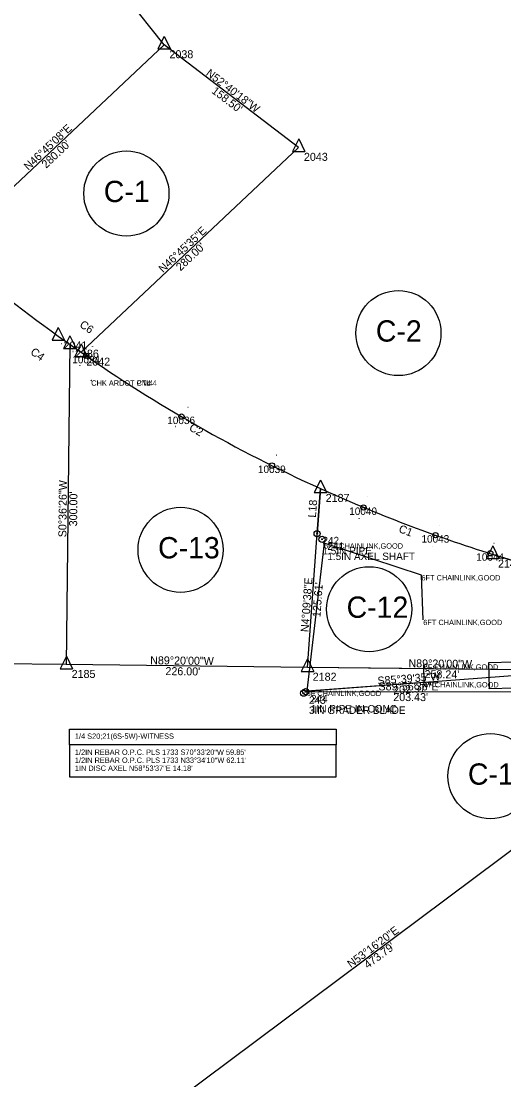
# Model space of a CAD drawing. Extents: x 1431802 to 1457777, y 1852108 to 1876350.
# Drawn here: x 1443202 to 1443655, y 1854558 to 1855549 of the extents above; entities that cross this region are included whole.
import ezdxf

# ---------------------------------------------------------------- set-up
doc = ezdxf.new("R2010")
doc.units = 0
for name, color, linetype in [('Default', 7, 'Continuous'), ('S_BUILDING', 7, 'Continuous'), ('S_CAL_CORNER', 7, 'Continuous'), ('S_CAL_CORNER_ANNOT', 7, 'Continuous'), ('S_EXISTING_ALIGNMENT', 7, 'Continuous'), ('S_EXISTING_ALIGNMENT_ANNOT', 7, 'Continuous'), ('S_FENCE', 7, 'Continuous'), ('S_FENCE_ANNOT', 7, 'Continuous'), ('S_IRON_PIN', 7, 'Continuous'), ('S_IRON_PIN_ANNOT', 7, 'Continuous'), ('S_MSC_PT_SYM', 7, 'Continuous'), ('S_PROPERTY', 7, 'Continuous'), ('S_PROPERTY_ANNOT', 7, 'Continuous'), ('S_PROPERTY_TEXT', 7, 'Continuous'), ('S_QSECTION', 7, 'Continuous'), ('S_QSECTION_ANNOT', 7, 'Continuous'), ('S_RDW_PT_SYM', 7, 'Continuous'), ('S_STR_PT_SYM', 7, 'Continuous'), ('S_SURVEY_TEXT_ANNOT', 7, 'Continuous')]:
    doc.layers.add(name, color=color, linetype=linetype)

msp = doc.modelspace()

# ---------------------------------------------------------------- linework, layer by layer
at = {"layer": 'Default'}
for points in [[(1443240.35, 1855247.27), (1443240.38, 1855247.31), (1443240.35, 1855247.27), (1443240.31, 1855247.3), (1443240.35, 1855247.27), (1443240.32, 1855247.23), (1443240.35, 1855247.27), (1443240.39, 1855247.24)], [(1443251.05, 1855239.66), (1443251.08, 1855239.71), (1443251.05, 1855239.66), (1443251.01, 1855239.69), (1443251.05, 1855239.66), (1443251.03, 1855239.62), (1443251.05, 1855239.66), (1443251.1, 1855239.64)], [(1443365.94, 1855166.79), (1443365.96, 1855166.83), (1443365.94, 1855166.79), (1443365.89, 1855166.81), (1443365.94, 1855166.79), (1443365.91, 1855166.74), (1443365.94, 1855166.79), (1443365.98, 1855166.76)], [(1443477.64, 1855090.52), (1443477.59, 1855090.52), (1443477.64, 1855090.52), (1443477.63, 1855090.47), (1443477.64, 1855090.52), (1443477.69, 1855090.51), (1443477.64, 1855090.52), (1443477.64, 1855090.57)], [(1443561.39, 1855074.57), (1443561.41, 1855074.62), (1443561.39, 1855074.57), (1443561.34, 1855074.59), (1443561.39, 1855074.57), (1443561.37, 1855074.53), (1443561.39, 1855074.57), (1443561.43, 1855074.56)]]:
    msp.add_lwpolyline(points, dxfattribs=at)
at = {"layer": 'S_BUILDING'}
for p, q in [((1443664.71, 1854948.82), (1443640.45, 1854948.13)), ((1443640.45, 1854948.13), (1443641.13, 1854923.94)), ((1443641.13, 1854923.94), (1443665.32, 1854924.65))]:
    msp.add_line(p, q, dxfattribs=at)
at = {"layer": 'S_CAL_CORNER'}
for p, q in [((1443336.55, 1855534.92), (1443330.67, 1855523.1)), ((1443336.55, 1855534.92), (1443342.36, 1855523.1)), ((1443330.67, 1855523.1), (1443342.36, 1855523.1)), ((1443462.59, 1855438.81), (1443456.71, 1855426.99)), ((1443462.59, 1855438.81), (1443468.4, 1855426.99)), ((1443456.71, 1855426.99), (1443468.4, 1855426.99)), ((1443237.26, 1855262.17), (1443231.39, 1855250.35)), ((1443237.26, 1855262.17), (1443243.08, 1855250.35)), ((1443231.39, 1855250.35), (1443243.08, 1855250.35)), ((1443248.01, 1855254.45), (1443242.14, 1855242.63)), ((1443248.01, 1855254.45), (1443253.83, 1855242.63)), ((1443242.14, 1855242.63), (1443253.83, 1855242.63)), ((1443258.61, 1855246.99), (1443252.73, 1855235.18)), ((1443258.61, 1855246.99), (1443264.42, 1855235.18)), ((1443252.73, 1855235.18), (1443264.42, 1855235.18)), ((1443483, 1855119.34), (1443477.13, 1855107.52)), ((1443483, 1855119.34), (1443477.13, 1855107.52)), ((1443483, 1855119.34), (1443488.82, 1855107.52)), ((1443483, 1855119.34), (1443488.82, 1855107.52)), ((1443477.13, 1855107.52), (1443488.82, 1855107.52)), ((1443477.13, 1855107.52), (1443488.82, 1855107.52)), ((1443644.51, 1855057.73), (1443638.64, 1855045.91)), ((1443644.51, 1855057.73), (1443638.64, 1855045.91)), ((1443644.51, 1855057.73), (1443650.33, 1855045.91)), ((1443644.51, 1855057.73), (1443650.33, 1855045.91)), ((1443638.64, 1855045.91), (1443650.33, 1855045.91)), ((1443638.64, 1855045.91), (1443650.33, 1855045.91)), ((1443244.83, 1854954.47), (1443238.96, 1854942.65)), ((1443244.83, 1854954.47), (1443250.65, 1854942.65)), ((1443470.82, 1854951.84), (1443464.94, 1854940.02)), ((1443470.82, 1854951.84), (1443464.94, 1854940.02)), ((1443470.82, 1854951.84), (1443476.63, 1854940.02)), ((1443470.82, 1854951.84), (1443476.63, 1854940.02)), ((1443238.96, 1854942.65), (1443250.65, 1854942.65)), ((1443464.94, 1854940.02), (1443476.63, 1854940.02)), ((1443464.94, 1854940.02), (1443476.63, 1854940.02))]:
    msp.add_line(p, q, dxfattribs=at)
at = {"layer": 'S_EXISTING_ALIGNMENT'}
for centre in [(1443263.49, 1855235.69), (1443352.7, 1855178.76), (1443437.52, 1855132.92), (1443523.35, 1855093.66), (1443590.8, 1855067.71), (1443642.19, 1855050.75)]:
    msp.add_circle(centre, 2.5, dxfattribs=at)
at = {"layer": 'S_FENCE'}
for p, q in [((1443486.36, 1855060.08), (1443470.09, 1854922.04)), ((1443577.66, 1855030.3), (1443486.36, 1855060.08)), ((1443579.37, 1854988.47), (1443577.66, 1855030.3)), ((1443580.24, 1854930.1), (1443579.85, 1854946.67)), ((1443470.09, 1854922.04), (1443580.24, 1854930.1))]:
    msp.add_line(p, q, dxfattribs=at)
at = {"layer": 'S_IRON_PIN'}
for centre, radius in [((1443479.84, 1855069.13), 2.91), ((1443479.84, 1855069.13), 0.411), ((1443479.84, 1855069.13), 0.262), ((1443479.84, 1855069.13), 0.212), ((1443479.84, 1855069.13), 0.145), ((1443479.84, 1855069.13), 0.0822), ((1443479.84, 1855069.13), 0.0581), ((1443484.43, 1855063.87), 2.91), ((1443484.43, 1855063.87), 0.411), ((1443484.43, 1855063.87), 0.262), ((1443484.43, 1855063.87), 0.212), ((1443484.43, 1855063.87), 0.145), ((1443484.43, 1855063.87), 0.0822), ((1443484.43, 1855063.87), 0.0581), ((1443469.08, 1854921.13), 2.91), ((1443467.24, 1854919.74), 2.91), ((1443467.24, 1854919.74), 0.411), ((1443467.24, 1854919.74), 0.262), ((1443467.24, 1854919.74), 0.212), ((1443467.24, 1854919.74), 0.145), ((1443467.24, 1854919.74), 0.0822), ((1443467.24, 1854919.74), 0.0581), ((1443469.08, 1854921.13), 0.411), ((1443469.08, 1854921.13), 0.262), ((1443469.08, 1854921.13), 0.212), ((1443469.08, 1854921.13), 0.145), ((1443469.08, 1854921.13), 0.0822), ((1443469.08, 1854921.13), 0.0581)]:
    msp.add_circle(centre, radius, dxfattribs=at)
at = {"layer": 'S_MSC_PT_SYM'}
for points in [[(1443268.11, 1855212.7), (1443268.11, 1855212.75), (1443268.11, 1855212.7), (1443268.06, 1855212.7), (1443268.11, 1855212.7), (1443268.11, 1855212.65), (1443268.11, 1855212.7), (1443268.17, 1855212.7)], [(1443268.12, 1855212.72), (1443268.12, 1855212.77), (1443268.12, 1855212.72), (1443268.07, 1855212.72), (1443268.12, 1855212.72), (1443268.12, 1855212.67), (1443268.12, 1855212.72), (1443268.17, 1855212.72)], [(1443268.13, 1855212.71), (1443268.13, 1855212.76), (1443268.13, 1855212.71), (1443268.08, 1855212.71), (1443268.13, 1855212.71), (1443268.13, 1855212.66), (1443268.13, 1855212.71), (1443268.18, 1855212.71)], [(1443268.13, 1855212.69), (1443268.13, 1855212.74), (1443268.13, 1855212.69), (1443268.08, 1855212.69), (1443268.13, 1855212.69), (1443268.13, 1855212.64), (1443268.13, 1855212.69), (1443268.18, 1855212.69)], [(1443268.13, 1855212.69), (1443268.13, 1855212.74), (1443268.13, 1855212.69), (1443268.08, 1855212.69), (1443268.13, 1855212.69), (1443268.13, 1855212.64), (1443268.13, 1855212.69), (1443268.18, 1855212.69)], [(1443268.13, 1855212.67), (1443268.13, 1855212.72), (1443268.13, 1855212.67), (1443268.08, 1855212.67), (1443268.13, 1855212.67), (1443268.13, 1855212.62), (1443268.13, 1855212.67), (1443268.18, 1855212.67)], [(1443268.15, 1855212.74), (1443268.15, 1855212.79), (1443268.15, 1855212.74), (1443268.09, 1855212.74), (1443268.15, 1855212.74), (1443268.15, 1855212.69), (1443268.15, 1855212.74), (1443268.2, 1855212.74)], [(1443268.15, 1855212.73), (1443268.15, 1855212.78), (1443268.15, 1855212.73), (1443268.1, 1855212.73), (1443268.15, 1855212.73), (1443268.15, 1855212.68), (1443268.15, 1855212.73), (1443268.2, 1855212.73)], [(1443268.15, 1855212.73), (1443268.15, 1855212.78), (1443268.15, 1855212.73), (1443268.1, 1855212.73), (1443268.15, 1855212.73), (1443268.15, 1855212.68), (1443268.15, 1855212.73), (1443268.2, 1855212.73)], [(1443268.15, 1855212.69), (1443268.15, 1855212.74), (1443268.15, 1855212.69), (1443268.1, 1855212.69), (1443268.15, 1855212.69), (1443268.15, 1855212.64), (1443268.15, 1855212.69), (1443268.2, 1855212.69)], [(1443486.36, 1855060.08), (1443486.36, 1855060.13), (1443486.36, 1855060.08), (1443486.31, 1855060.08), (1443486.36, 1855060.08), (1443486.36, 1855060.03), (1443486.36, 1855060.08), (1443486.42, 1855060.08)], [(1443577.66, 1855030.3), (1443577.66, 1855030.35), (1443577.66, 1855030.3), (1443577.61, 1855030.3), (1443577.66, 1855030.3), (1443577.66, 1855030.25), (1443577.66, 1855030.3), (1443577.71, 1855030.3)], [(1443579.37, 1854988.47), (1443579.37, 1854988.52), (1443579.37, 1854988.47), (1443579.32, 1854988.47), (1443579.37, 1854988.47), (1443579.37, 1854988.42), (1443579.37, 1854988.47), (1443579.42, 1854988.47)], [(1443579.85, 1854946.67), (1443579.85, 1854946.72), (1443579.85, 1854946.67), (1443579.8, 1854946.67), (1443579.85, 1854946.67), (1443579.85, 1854946.62), (1443579.85, 1854946.67), (1443579.9, 1854946.67)], [(1443580.24, 1854930.1), (1443580.24, 1854930.15), (1443580.24, 1854930.1), (1443580.19, 1854930.1), (1443580.24, 1854930.1), (1443580.24, 1854930.05), (1443580.24, 1854930.1), (1443580.29, 1854930.1)], [(1443470.09, 1854922.04), (1443470.09, 1854922.09), (1443470.09, 1854922.04), (1443470.04, 1854922.04), (1443470.09, 1854922.04), (1443470.09, 1854921.99), (1443470.09, 1854922.04), (1443470.14, 1854922.04)]]:
    msp.add_lwpolyline(points, dxfattribs=at)
at = {"layer": 'S_PROPERTY'}
for p, q in [((1443336.46, 1855526.94), (1443149.86, 1855761.85)), ((1443132.51, 1855335.1), (1443336.46, 1855526.94)), ((1443462.5, 1855430.83), (1443336.46, 1855526.94)), ((1443258.52, 1855239.01), (1443462.5, 1855430.83)), ((1443247.92, 1855246.47), (1443244.74, 1854946.49)), ((1443482.91, 1855111.36), (1443479.84, 1855069.13)), ((1443479.84, 1855069.13), (1443482.91, 1855111.36)), ((1443470.73, 1854943.86), (1443479.84, 1855069.13)), ((1443470.73, 1854943.86), (1443479.84, 1855069.13)), ((1443730.75, 1855022.75), (1443644.42, 1855049.75)), ((1443644.42, 1855049.75), (1443691.79, 1855034.93)), ((1443644.42, 1855049.75), (1443691.79, 1855034.93)), ((1443244.74, 1854946.49), (1442408.47, 1854956.22)), ((1443671.13, 1854941.53), (1443470.73, 1854943.86)), ((1443671.47, 1854936.49), (1443469.08, 1854921.13)), ((1443469.08, 1854921.13), (1443672.51, 1854920.93)), ((1443347.68, 1854538.17), (1443727.41, 1854821.5))]:
    msp.add_line(p, q, dxfattribs=at)
for centre in [(1443301.02, 1855387.69), (1443556.05, 1855257.01), (1443351.91, 1855053.97), (1443528.65, 1854998.3), (1443642.38, 1854841.97)]:
    msp.add_circle(centre, 39.9, dxfattribs=at)
for centre, radius, start, end in [((1444500.97, 1856997.21), 2152.97, 230.53452, 234.05567), ((1444065.88, 1856397.14), 1411.77, 234.05567, 234.59274), ((1444065.88, 1856397.14), 1411.77, 234.59274, 235.11858), ((1444065.88, 1856397.14), 1411.77, 235.11858, 245.61073), ((1444065.88, 1856397.14), 1411.77, 245.61073, 252.63058), ((1444065.88, 1856397.14), 1411.77, 245.61073, 252.63058)]:
    msp.add_arc(centre, radius, start, end, dxfattribs=at)
at = {"layer": 'S_PROPERTY_TEXT'}
for points in [[(1443247.75, 1854886.04), (1443497.74, 1854886.04), (1443497.74, 1854871.41), (1443247.75, 1854871.41)], [(1443247.75, 1854841.27), (1443497.74, 1854841.27), (1443497.74, 1854871.41), (1443247.75, 1854871.41)]]:
    msp.add_lwpolyline(points, close=True, dxfattribs=at)
at = {"layer": 'S_QSECTION'}
for p, q in [((1443470.73, 1854943.86), (1443244.74, 1854946.49)), ((1443728.95, 1854940.85), (1443470.73, 1854943.86))]:
    msp.add_line(p, q, dxfattribs=at)
at = {"layer": 'S_RDW_PT_SYM'}
for points in [[(1443269.37, 1855244.31), (1443269.37, 1855244.36), (1443269.37, 1855244.31), (1443269.32, 1855244.31), (1443269.37, 1855244.31), (1443269.37, 1855244.26), (1443269.37, 1855244.31), (1443269.42, 1855244.31)], [(1443257.38, 1855226.76), (1443257.38, 1855226.81), (1443257.38, 1855226.76), (1443257.33, 1855226.76), (1443257.38, 1855226.76), (1443257.38, 1855226.71), (1443257.38, 1855226.76), (1443257.43, 1855226.76)], [(1443358.77, 1855187.6), (1443358.77, 1855187.66), (1443358.77, 1855187.6), (1443358.72, 1855187.6), (1443358.77, 1855187.6), (1443358.77, 1855187.55), (1443358.77, 1855187.6), (1443358.82, 1855187.6)], [(1443346.99, 1855169.59), (1443346.99, 1855169.64), (1443346.99, 1855169.59), (1443346.94, 1855169.59), (1443346.99, 1855169.59), (1443346.99, 1855169.54), (1443346.99, 1855169.59), (1443347.04, 1855169.59)], [(1443441.63, 1855142.55), (1443441.63, 1855142.6), (1443441.63, 1855142.55), (1443441.58, 1855142.55), (1443441.63, 1855142.55), (1443441.63, 1855142.51), (1443441.63, 1855142.55), (1443441.68, 1855142.55)], [(1443434.07, 1855122.29), (1443434.07, 1855122.34), (1443434.07, 1855122.29), (1443434.02, 1855122.29), (1443434.07, 1855122.29), (1443434.07, 1855122.24), (1443434.07, 1855122.29), (1443434.12, 1855122.29)], [(1443527.29, 1855103.54), (1443527.29, 1855103.58), (1443527.29, 1855103.54), (1443527.24, 1855103.54), (1443527.29, 1855103.54), (1443527.29, 1855103.48), (1443527.29, 1855103.54), (1443527.34, 1855103.54)], [(1443519.2, 1855083.17), (1443519.2, 1855083.22), (1443519.2, 1855083.17), (1443519.15, 1855083.17), (1443519.2, 1855083.17), (1443519.2, 1855083.12), (1443519.2, 1855083.17), (1443519.25, 1855083.17)], [(1443594.36, 1855077), (1443594.36, 1855077.05), (1443594.36, 1855077), (1443594.31, 1855077), (1443594.36, 1855077), (1443594.36, 1855076.95), (1443594.36, 1855077), (1443594.41, 1855077)], [(1443588.05, 1855057.16), (1443588.05, 1855057.21), (1443588.05, 1855057.16), (1443588, 1855057.16), (1443588.05, 1855057.16), (1443588.05, 1855057.11), (1443588.05, 1855057.16), (1443588.1, 1855057.16)], [(1443645.63, 1855060.19), (1443645.63, 1855060.24), (1443645.63, 1855060.19), (1443645.58, 1855060.19), (1443645.63, 1855060.19), (1443645.63, 1855060.14), (1443645.63, 1855060.19), (1443645.68, 1855060.19)], [(1443640.41, 1855039.87), (1443640.41, 1855039.92), (1443640.41, 1855039.87), (1443640.36, 1855039.87), (1443640.41, 1855039.87), (1443640.41, 1855039.82), (1443640.41, 1855039.87), (1443640.46, 1855039.87)]]:
    msp.add_lwpolyline(points, dxfattribs=at)
at = {"layer": 'S_STR_PT_SYM'}
for points in [[(1443640.45, 1854948.13), (1443640.45, 1854948.18), (1443640.45, 1854948.13), (1443640.4, 1854948.13), (1443640.45, 1854948.13), (1443640.45, 1854948.08), (1443640.45, 1854948.13), (1443640.5, 1854948.13)], [(1443641.13, 1854923.94), (1443641.13, 1854923.99), (1443641.13, 1854923.94), (1443641.08, 1854923.94), (1443641.13, 1854923.94), (1443641.13, 1854923.89), (1443641.13, 1854923.94), (1443641.18, 1854923.94)]]:
    msp.add_lwpolyline(points, dxfattribs=at)

# ---------------------------------------------------------------- texts
at = {"layer": 'S_CAL_CORNER_ANNOT'}
for s, p in [('2038', (1443341.46, 1855514.44)), ('2043', (1443467.5, 1855418.33)), ('2041', (1443242.17, 1855241.69)), ('2186', (1443252.92, 1855233.97)), ('2042', (1443263.52, 1855226.51)), ('2187', (1443487.91, 1855098.86)), ('2144', (1443649.42, 1855037.25)), ('2185', (1443249.74, 1854933.99)), ('2182', (1443475.73, 1854931.36))]:
    msp.add_text(s, height=7.5, dxfattribs=at).set_placement(p)
at = {"layer": 'S_EXISTING_ALIGNMENT_ANNOT'}
for s, p in [('10034', (1443250.37, 1855228.69)), ('10036', (1443339.39, 1855171.76)), ('10039', (1443424.38, 1855125.92)), ('10040', (1443509.93, 1855086.66)), ('10043', (1443577.69, 1855060.71)), ('10044', (1443629.07, 1855043.75))]:
    msp.add_text(s, height=7, dxfattribs=at).set_placement(p)
at = {"layer": 'S_FENCE_ANNOT'}
for s, p in [('6FT CHAINLINK,GOOD', (1443486.36, 1855055.08)), ('6FT CHAINLINK,GOOD', (1443577.66, 1855025.3)), ('6FT CHAINLINK,GOOD', (1443579.37, 1854983.47)), ('6F CHAINLINK,GOOD', (1443579.85, 1854941.67)), ('6F CHAINLINK,GOOD', (1443580.24, 1854925.1)), ('6F CHAINLINK,GOOD', (1443470.09, 1854917.04))]:
    msp.add_text(s, height=5, dxfattribs=at).set_placement(p)
at = {"layer": 'S_IRON_PIN_ANNOT'}
for s, p in [('242', (1443484.84, 1855059.13)), ('1.5IN PIPE', (1443484.84, 1855049.63)), ('241', (1443489.43, 1855053.87)), ('1.5IN AXEL SHAFT', (1443489.43, 1855044.37)), ('243', (1443472.24, 1854909.75)), ('244', (1443474.08, 1854911.13)), ('3IN GRADER BLADE', (1443472.24, 1854900.25)), ('1IN PIPE IN CONC', (1443474.08, 1854901.63))]:
    msp.add_text(s, height=7, dxfattribs=at).set_placement(p)
at = {"layer": 'S_PROPERTY'}
for s, p in [('C-1', (1443279.88, 1855379.68)), ('C-2', (1443534.92, 1855249.01)), ('C-13', (1443330.77, 1855045.97)), ('C-12', (1443507.51, 1854990.29)), ('C-11', (1443621.24, 1854833.96))]:
    msp.add_text(s, height=19.95, dxfattribs=at).set_placement(p)
at = {"layer": 'S_PROPERTY_ANNOT'}
for s, rotation, p in [('N52%%d40\'18"W', 322.67163, (1443375.02, 1855499.11)), ("158.50'", 322.67163, (1443380.32, 1855482.49)), ('N46%%d45\'08"E', 43.24775, (1443209.2, 1855408.95)), ("280.00'", 43.24775, (1443225.81, 1855410.85)), ('N46%%d45\'35"E', 43.24022, (1443335.43, 1855313.06)), ("280.00'", 43.24022, (1443351.83, 1855314.75)), ('C6', 324.85566, (1443256.54, 1855263.38)), ('C4', 324.32421, (1443210.45, 1855237.86)), ('C2', 330.36466, (1443359.16, 1855166.33)), ('S0%%d36\'26"W', 89.39276, (1443244.76, 1855065.67)), ("300.00'", 89.39276, (1443254.87, 1855075.96)), ('L18', 85.83953, (1443478.67, 1855083.92)), ('C1', 339.12066, (1443555.7, 1855070.77)), ('N4%%d09\'38"E', 85.83953, (1443471.86, 1854976.67)), ("125.61'", 85.83953, (1443482.91, 1854990.72)), ('S85%%d39\'35"W', 4.34033, (1443536.73, 1854927.52)), ('S89%%d56\'36"E', 359.94339, (1443537.37, 1854922.31)), ("202.97'", 4.34033, (1443551.44, 1854918.61)), ("203.43'", 359.94339, (1443551.24, 1854912.3)), ('N53%%d16\'20"E', 36.72784, (1443511.61, 1854662.05)), ("473.79'", 36.72784, (1443527.35, 1854661.31))]:
    msp.add_text(s, height=7.5, rotation=rotation, dxfattribs=at).set_placement(p)
at = {"layer": 'S_PROPERTY_TEXT'}
for s, p in [('1/4 S20;21(6S-5W)-WITNESS', (1443252.79, 1854876.94)), ('1/2IN REBAR O.P.C. PLS 1733 S70%%D33\'20"W 59.85\'', (1443252.79, 1854861.94)), ('1/2IN REBAR O.P.C. PLS 1733 N33%%D34\'10"W 62.11\'', (1443252.79, 1854854.44)), ('1IN DISC AXEL N58%%D53\'37"E 14.18\'', (1443252.79, 1854846.94))]:
    msp.add_text(s, height=5, dxfattribs=at).set_placement(p)
at = {"layer": 'S_QSECTION_ANNOT'}
for s, p in [('N89%%d20\'00"W', (1443323.32, 1854946.82)), ("226.00'", (1443337.62, 1854936.66)), ('N89%%d20\'00"W', (1443565.43, 1854944.01)), ("258.24'", (1443580.49, 1854933.83))]:
    msp.add_text(s, height=7.5, rotation=359.33328, dxfattribs=at).set_placement(p)
at = {"layer": 'S_SURVEY_TEXT_ANNOT'}
for s, p in [('CHK ARDOT PN4', (1443268.11, 1855207.7)), ('CHK ARDOT CTL 4', (1443268.12, 1855207.72)), ('CHK ARDOT PN 4', (1443268.13, 1855207.71)), ('CHK ARDOT PN 4', (1443268.13, 1855207.69)), ('CHK ARDOT PN 4', (1443268.13, 1855207.69)), ('CHK ARDOT PN 4', (1443268.13, 1855207.67)), ('CHK ARDOT PN 4', (1443268.15, 1855207.74)), ('CHK ARDOT PN4', (1443268.15, 1855207.73)), ('CHK ARDOT PN 4', (1443268.15, 1855207.73)), ('CHK ARDOT PN 4', (1443268.15, 1855207.69))]:
    msp.add_text(s, height=5, dxfattribs=at).set_placement(p)

doc.saveas('drawing.dxf')
